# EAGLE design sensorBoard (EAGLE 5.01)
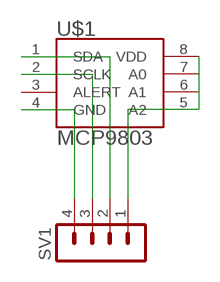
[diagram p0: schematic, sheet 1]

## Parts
SV1  MA04-1  [MA04-1]
U$1  MCP9803  [SO-08M]

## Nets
N$1: SV1.3 U$1.2(SCLK)
N$2: SV1.2 U$1.1(SDA)
N$3: SV1.4 U$1.4(GND)
N$4: SV1.1 U$1.5(A2) U$1.8(VDD)
Unconnected: U$1.3(ALERT) U$1.6(A1) U$1.7(A0)

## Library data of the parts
SV1 = con-lstb:MA04-1: PIN HEADER
U$1 = marios:MCP9803: MCP9803 2 Wire Temperature Sensor Microchip MCP9803 2 Wire High Accuracy Temperature Sensor http://ww1.microchip.com/downloads/en/DeviceDoc/21909b.pdf

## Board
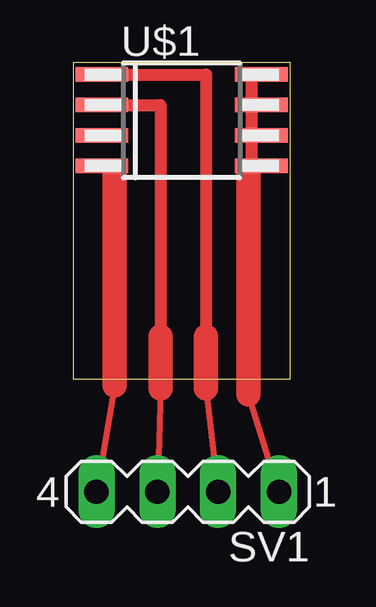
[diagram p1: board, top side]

Size 9.07 x 13.2 mm. Coordinates in mm from the lower left corner, seen from the top.
Outline: 0,0 9.07,0 9.07,13.2 0,13.2 0,0
Copper layers (1*16): Top 0.035mm / dielectric 1.5mm / Bottom 0.035mm
Design rules "default": minimum track width 10mil, minimum drill 24mil, track to track 8mil, track to pad 8mil, pad to pad 8mil, via to via 8mil, smd to smd 8mil, copper to edge 40mil, drill to drill 8mil, minimum pad ring 10mil, minimum via ring 8mil, stop-mask expansion 4mil, vias tented up to drill 0mil, thermal gap 10mil

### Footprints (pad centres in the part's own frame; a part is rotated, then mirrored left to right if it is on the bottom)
MA04-1 = drill 1.016 long: 1 -3.81,0; 2 -1.27,0; 3 1.27,0; 4 3.81,0
SO-08M = smd 0.6 x 2.2: 1 -1.905,-3.33; 2 -0.635,-3.33; 3 0.635,-3.33; 4 1.905,-3.33; 5 1.905,3.33; 6 0.635,3.33; 7 -0.635,3.33; 8 -1.905,3.33

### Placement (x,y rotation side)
SV1  4.79,-4.7 180 top  (outside the outline)
U$1  4.53,10.79 270 top

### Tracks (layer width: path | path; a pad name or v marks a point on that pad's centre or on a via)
N$1
  Top 0.254: 3.64,-0.39 SV1.3
  Top 0.508: U$1.2 3.64,11.43 3.64,1.77
  Top 1.016: 3.64,1.77 3.64,-0.39
N$2
  Top 0.254: 5.55,-0.39 SV1.2
  Top 0.508: U$1.1 5.55,12.7 5.55,1.77
  Top 1.016: 5.55,1.77 5.55,-0.39
N$3
  Top 0.254: U$1.4 1.99,8.88 1.74,8.63 | 1.74,-0.26 SV1.4
  Top 1.016: 1.74,8.63 1.74,-0.26
N$4
  Top 0.254: SV1.1 7.33,-0.64
  Top 0.406: 7.46,8.88 U$1.5
  Top 0.508: 7.46,8.88 7.46,12.7
  Top 0.61: 7.46,12.7 U$1.8 | 7.33,8.63 7.46,8.88
  Top 1.016: 7.33,-0.64 7.33,8.63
